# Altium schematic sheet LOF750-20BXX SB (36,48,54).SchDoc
size A4; Revision: A; SheetNumber: 1; SheetTotal: 1
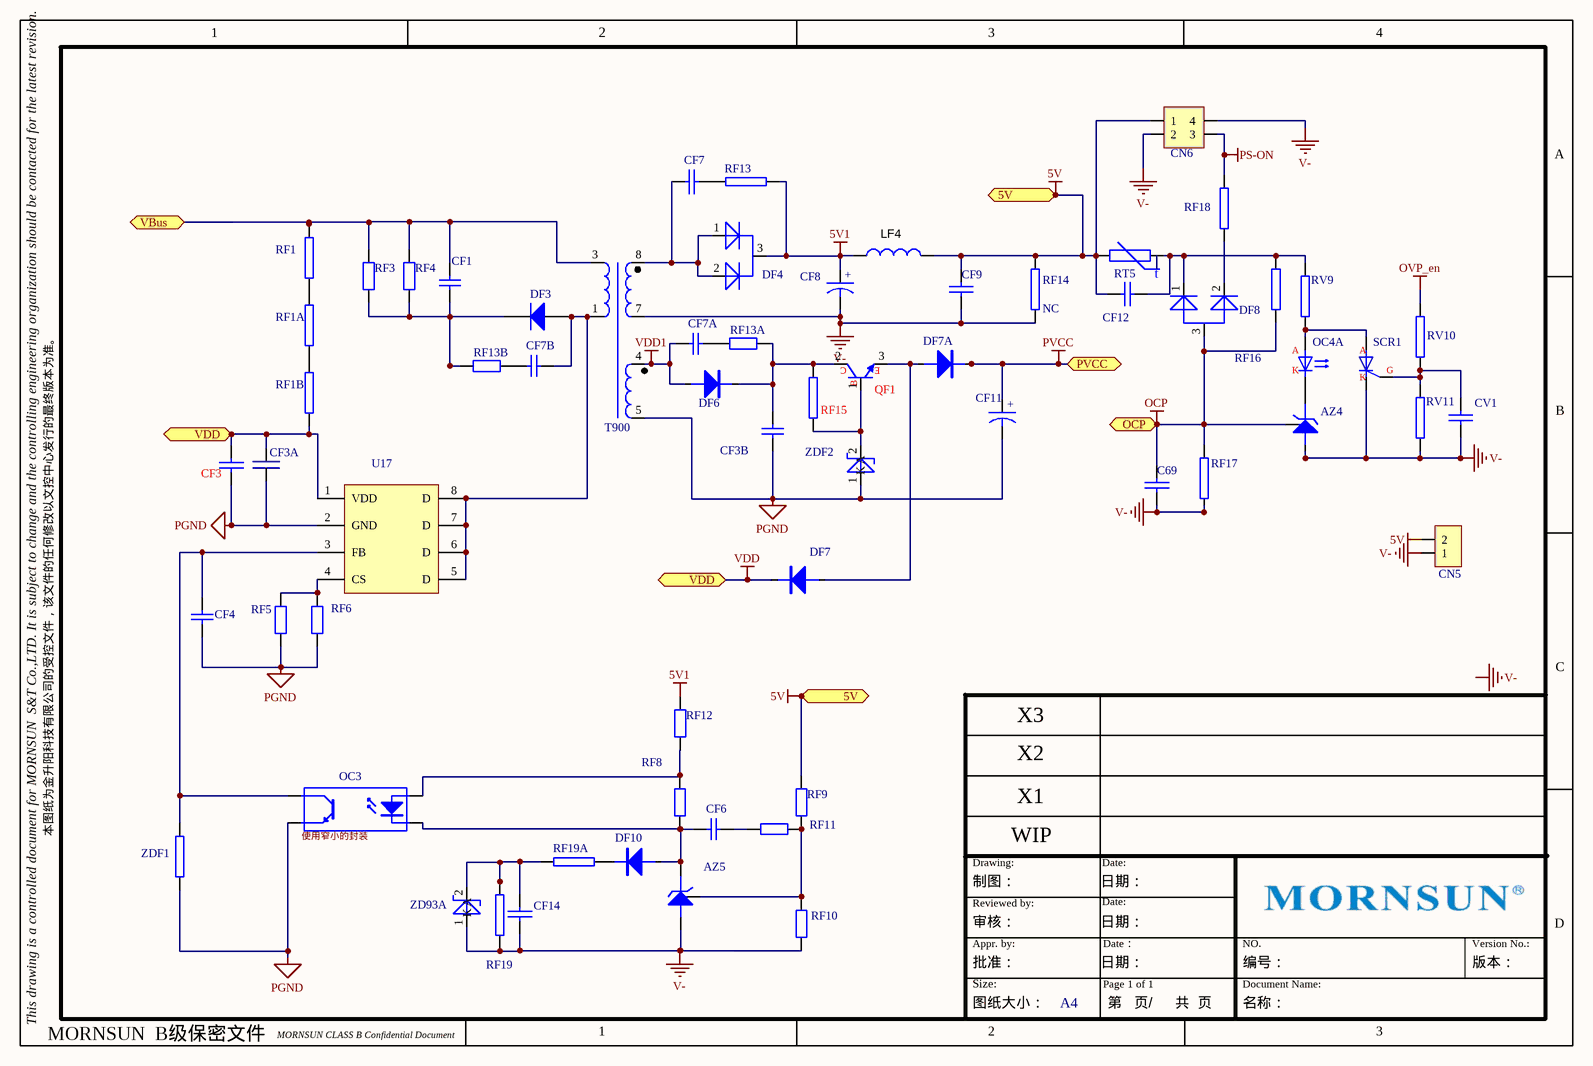
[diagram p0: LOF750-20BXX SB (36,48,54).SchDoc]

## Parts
AZ4  AZ431AN/SOT-23  [SOT-23A]  (value not drawn)
AZ5  (no value)  [SOT-23A]
C69  0805  [SC-0805]  (value not drawn)
CF1  2.2nF (222) 10% 2000V  [SC-0805]  (value not drawn)
CF3  1206  [SC-1206]  (value not drawn)
CF3A  0603  [SC-0603]  (value not drawn)
CF3B  (no value)  [SC-1206]
CF4  100pF (101) 5% 50V  [SC-0603]  (value not drawn)
CF6  100nF  [SC-0603]  (value not drawn)
CF7  0805  [SC-0805]  (value not drawn)
CF7A  (no value)  [SC-1206]
CF7B  (no value)  [SC-1206]
CF8  6.3*8  [EC-2.5-6.3X11.0-V]  (value not drawn)
CF9  1206  [SC-1206]  (value not drawn)
CF11  100uF/35V/6.3*11  [EC-2.5-6.3X11.0-V]  (value not drawn)
CF12  0603  [SC-0603]  (value not drawn)
CF14  0603  [SC-0603]  (value not drawn)
CN5  MHDR1X2  [CON-2.5-2P-S(5*6)]  (value not drawn)
CN6  MHDR1X2  [CON-2-02P-D]  (value not drawn)
CV1  0603  [SC-0603]  (value not drawn)
DF3  F7A  [SOD-123&SD-1206]  (value not drawn)
DF4  S10A45S/TO-277  [SD-Z3PAK]  (value not drawn)
DF6  2A/200V/SOD-123H  [SOD-123&SD-1206]  (value not drawn)
DF7  2A/200V/SOD-323  [SOD-323]  (value not drawn)
DF7A  2A/200V/SOD-123  [SOD-123&SD-1206]  (value not drawn)
DF8  SOT23  [WSOT-23B]  (value not drawn)
DF10  SOD-323  [SOD-323]  (value not drawn)
LF4  12050306  [IND2-2.0-5.2-C]  (value not drawn)
OC3  (no value)  [SOPT-101]
OC4  (no value)  [SOPT-101]  (part A of 2)
QF1  BCX56/SOT89  [SOT-89]  (value not drawn)
RF1  100K/1206  [SR-1206]  (value not drawn)
RF1A  100K/1206  [SR-1206]  (value not drawn)
RF1B  100K/1206  [SR-1206]  (value not drawn)
RF3  100KΩ (1003) ±1%  [SR-0805]  (value not drawn)
RF4  100KΩ (1003) ±1%  [SR-0805]  (value not drawn)
RF5  1.8Ω (1R80) ±1%  [SR-0805]  (value not drawn)
RF6  1.8Ω (1R80) ±1%  [SR-0805]  (value not drawn)
RF8  5.1KΩ (5101) ±1%  [SR-0603]  (value not drawn)
RF9  47KΩ (4702) ±1%  [SR-0603]  (value not drawn)
RF10  12.4KΩ (1202) ±1%  [SR-0603]  (value not drawn)
RF11  1KΩ (1001) ±1%  [SR-0603]  (value not drawn)
RF12  2.4KΩ (2401) ±1%  [SR-0603]  (value not drawn)
RF13  1206  [SR-1206]  (value not drawn)
RF13A  100KΩ (1003) ±1%  [SR-0805]  (value not drawn)
RF13B  100KΩ (1003) ±1%  [SR-0805]  (value not drawn)
RF14  PN: NC  [SR-1206]  (hidden comment: 1206)
RF15  0805  [SR-0805]  (value not drawn)
RF16  180K/0603  [SR-0603]  (value not drawn)
RF17  680k/0603  [SR-0603]  (value not drawn)
RF18  100K/0603  [SR-0603]  (value not drawn)
RF19  10R/0603  [SR-0603]  (value not drawn)
RF19A  10R/0603  [SR-0603]  (value not drawn)
RT5  RT  [CON-2.0-2P-S(6.2*4.8)]  (value not drawn)
RV9  1206  [SR-1206]  (value not drawn)
RV10  0603  [SR-0603]  (value not drawn)
RV11  0805  [SR-0805]  (value not drawn)
SCR1  SOT23  [SOT-23A]  (value not drawn)
T900  TRA4  [TR10-EE16/9]  (value not drawn)
U17  SCM1733ASA  [SOP8-1.27]  (value not drawn)
ZD93A  SOD-123  [SOD-323]  (value not drawn)
ZDF1  0603  [SR-0603]  (value not drawn)
ZDF2  SOD-123  [SOD-123&SD-1206]  (value not drawn)

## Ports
5V (bidir), OCP, PVCC (bidir), VBus (bidir), VDD (bidir)

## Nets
5V: CF9.2 CF12.2 CN5.2 CN6.1 LF4.2 RF9.2 RF14.2 RT5.2 ; port 5V
5V1: CF8.1 DF4.3(COM) LF4.1 RF12.1 RF13.1
OCP: AZ4.1 C69.2 DF8.3(COM) RF16.1 RF17.2 ; port OCP
OVP_en: RV10.1
PGND: CF3.2 CF3A.1 CF3B.1 CF4.1 CF11.2 OC3.3(E) RF5.1 RF6.1 T900.5 U17.2(GND) ZDF1.2 ZDF2.1(A)
PS-ON: CN6.3 RF18.2
PVCC: CF11.1 DF7A.2(K) ; port PVCC
V-: AZ4.2 AZ5.2 C69.1 CF8.2 CF9.1 CF14.2 CN5.1 CN6.2 CN6.4 CV1.1 RF10.1 RF14.1 RF17.1 RF19.2 RV11.2 SCR1.1(K) T900.7 ZD93A.1(A)
VDD: CF3.1 CF3A.2 DF7.2(K) RF1B.1 U17.1(VDD) ; port VDD
VDD1: CF7A.2 DF6.1(A) T900.4
VBus: CF1.2 RF1.2 RF3.2 RF4.2 T900.3 ; port VBus
NetAZ4_3: AZ4.3 OC4.2(K)
NetAZ5_1: AZ5.1 RF9.1 RF10.2 RF11.2
NetAZ5_3: AZ5.3 CF6.1 DF10.1(A) OC3.2(K) RF8.1
NetCF1_1: CF1.1 DF3.2(K) RF3.1 RF4.1 RF13B.2
NetCF3B_2: CF3B.2 DF6.2(K) QF1.2(C) RF13A.1 RF15.1
NetCF4_2: CF4.2 OC3.4(C) U17.3(FB) ZDF1.1
NetCF6_2: CF6.2 RF11.1
NetCF7_1: CF7.1 RF13.2
NetCF7_2: CF7.2 DF4.1(A) DF4.2(A) T900.8
NetCF7A_1: CF7A.1 RF13A.2
NetCF7B_1: CF7B.1 DF3.1(A) T900.1 U17.5(D) U17.6(D) U17.7(D) U17.8(D)
NetCF7B_2: CF7B.2 RF13B.1
NetCF12_1: CF12.1 DF8.1(K) RF16.2 RT5.1 RV9.1
NetCF14_1: CF14.1 RF19.1 RF19A.1 ZD93A.2(K)
NetCV1_2: CV1.2 RV10.2 RV11.1 SCR1.3(G)
NetDF7_1: DF7.1(A) DF7A.1(A) QF1.3(E)
NetDF8_2: DF8.2(K) RF18.1
NetDF10_2: DF10.2(K) RF19A.2
NetOC3_1: OC3.1(A) RF8.2 RF12.2
NetOC4_1: OC4.1(A) RV9.2 SCR1.2(A)
NetQF1_1: QF1.1(B) RF15.2 ZDF2.2(K)
NetRF1_1: RF1.1 RF1A.2
NetRF1A_1: RF1A.1 RF1B.2
NetRF5_2: RF5.2 RF6.2 U17.4(CS)

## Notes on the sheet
- 1
- 2
- 3
- 4
- A
- B
- X3
- C
- X2
- 本图纸为金升阳科技有限公司的受控文件，该文件的任何修改以文控中心发行的最终版本为准。
- (near OC3) 使用窄小的封装
- Drawing:
- WIP
- X1
- Date:
- Reviewed by:
- 审核：
- 制图：
- 日期：
- D
- Appr. by:
- Size:
- 批准：
- Page 1 of 1
- Date：
- Document Name:
- NO.
- 编号：
- Version No.:
- 版本：
- This drawing is a controlled document for MORNSUN  S&T Co.,LTD. It is subject to change and the controlling engineering organization should be contacted for the latest revision.
- MORNSUN  B级保密文件
- MORNSUN CLASS B Confidential Document
- 图纸大小：
- A4
- 第   页/
- 共  页
- 名称：
- Labels drawn without touching a wire or pin: V-

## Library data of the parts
AZ4 AZ5 = 431: MPN: AZ431AN-ATRE1; PN: 32000001
C69 CF3 CF7 CF9 CF12 CF14 CV1 = CAP: 103K/50V/0603/X7R; PN: 30010146
CF1 = 1206 1nF (102) 10% 500V: 贴片电容; Valu: 2.2nF-2000V; PN: 30010243
CF3A = CAP-1: 102K/50V/0603/X7R; PN: 30010149
CF3B = 0805 470pF (471) 10% 50V: 贴片电容; PN: 30010251
CF4 = 0603 100pF (101) 5% 50V: 贴片电容; PN: 30010180
CF6 = Cap Semi: Capacitor (Semiconductor SIM Model); Value: 100nF (104) ±10% 50V; PN: 30000091
CF7A CF7B = 1206 1nF (102) 10% 500V: 贴片电容; Valu: 0805; PN: 30010243
CF8 CF11 = CAPACITOR POL: Capacitor; Mfr: Samxon; MPN: ESK228M1VK25RRSRP; APN: 30030042
CN5 = Pin2
CN6 = Pin2X2
DF3 = SOD-123 B5819W  SL: 肖特基二极管; PN: 31005029
DF4 = Diode BAV70
DF6 DF7 DF7A DF10 = DIODE: MPN: SK110; PN: 31000046
DF8 = Diode BAW56
LF4 = 7840-09-0014: PN: 52104014; APN: ??
OC3 = EL357N(B)(TA)-G_[C6649]: 贴片光耦; PN: 34000013
OC4 = OC
QF1 = NPN: NPN Transistor
RF1 RF1A RF1B = RES1: 2.2MΩ 1/8W ±1% 0805; PN: 35002037
RF3 RF4 = 1206 100KΩ (1003) 1%: 贴片电阻; Valu: 240K; PN: 35001015
RF5 RF6 = 1206 1Ω (1R00) 1%: 贴片电阻; PN: 35001021
RF8 = 0603 5.1KΩ (5101) 1%: 贴片电阻; PN: 35000071; Valu: 5.1K
RF9 = 0805 47KΩ (4702) 1%: 贴片电阻; PN: 35002014; Valu: 47K
RF10 = 0603 12KΩ (1202) 1%: 贴片电阻; PN: 35000042; Valu: 12.4K
RF11 = 0603 1KΩ (1001) 1%: 贴片电阻; Valu: 1K
RF12 = 0603 2.4KΩ (2401) 1%: 贴片电阻; Valu: 2.4K; PN: 35000081
RF13 RF16-RF18 = RES1: 2.2MΩ 1/8W ±1% 0805; PN: NC
RF13A RF13B = 1206 100KΩ (1003) 1%: 贴片电阻; Valu: 0805; PN: 35001015
RF14 RV9-RV11 = RES1: 2.2MΩ 1/8W ±1% 0805
RF15 = RES1: PN: 35000010
RF19 RF19A = RES1
SCR1 = SCR
T900 = Trans4
U17 = 2C2544: PN: 32010156
ZD93A ZDF2 = Diode 稳压: Zener Diode
ZDF1 = RES1: PN: 35000027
